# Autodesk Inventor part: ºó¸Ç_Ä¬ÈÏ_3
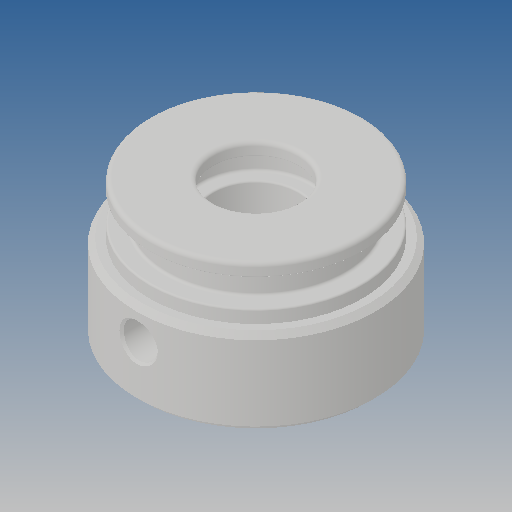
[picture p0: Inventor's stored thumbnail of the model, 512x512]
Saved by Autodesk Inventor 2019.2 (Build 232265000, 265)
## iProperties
Created: 2013-03
Part Number: ºó¸Ç_Ä¬ÈÏ_3
Material: Ogólny
Document SubType Name: Modeling
Designer: CADENGINEERING4
Density: 1 g/cm^3
Appearance: Domyślna
Author: CADENGINEERING4
Revision Number: ÈÎºÎ
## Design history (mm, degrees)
feature "NONE"
node "Bryła1"
